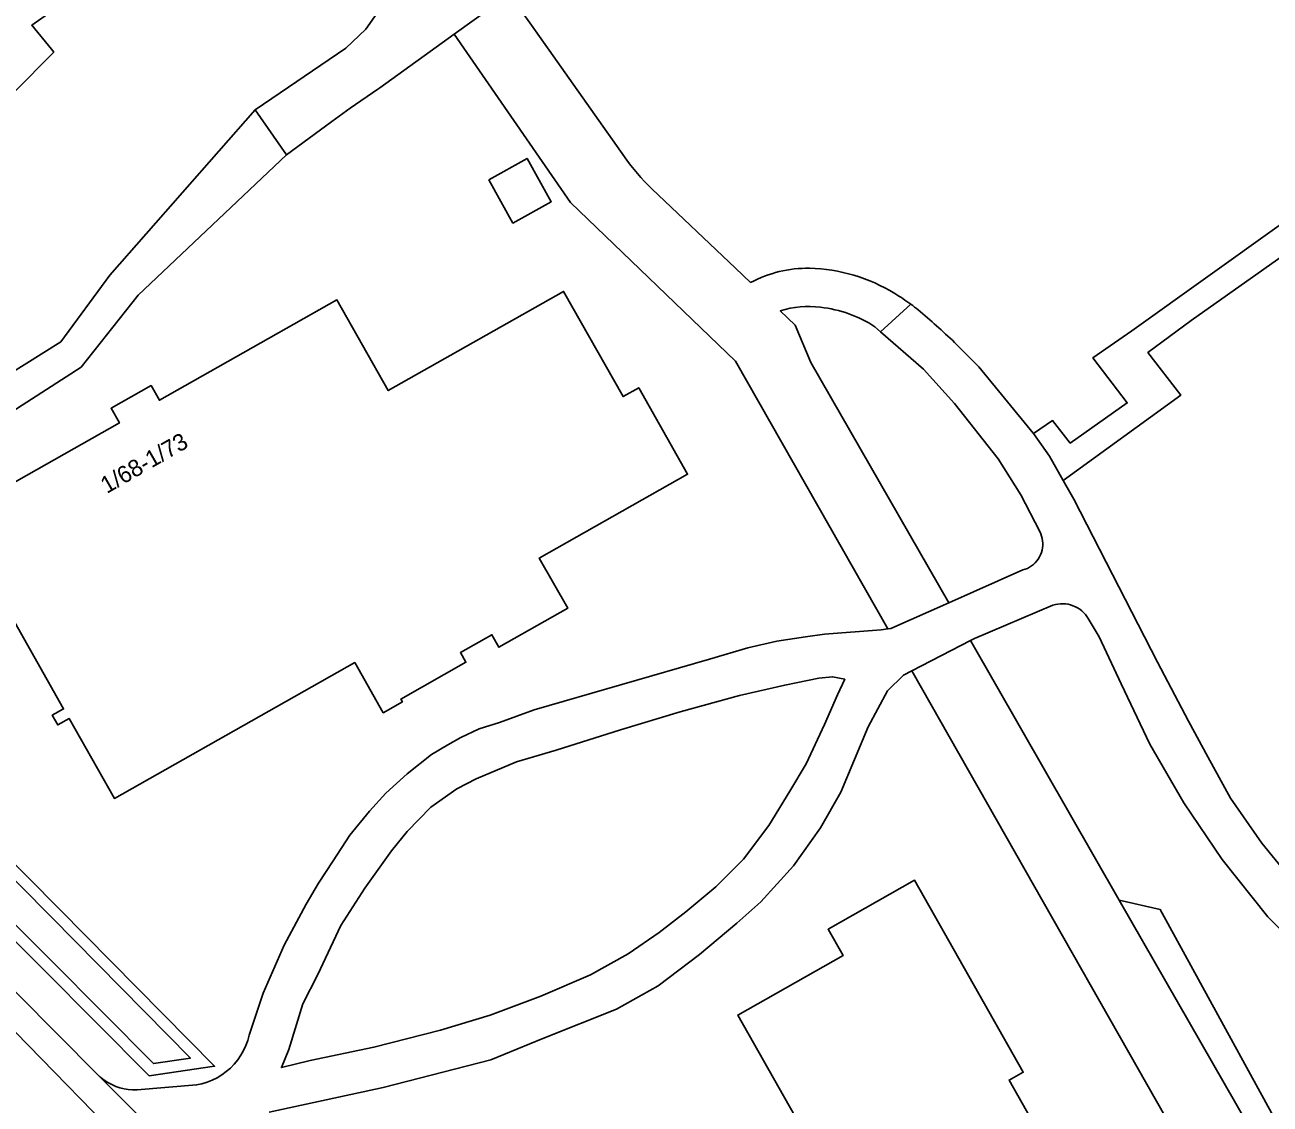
# Model space of a CAD drawing. Extents: x 162788 to 163838, y 385791 to 386523.
# Drawn here: x 162998.4 to 163072, y 386148.1 to 386211.9 of the extents above; entities that cross this region are included whole.
import ezdxf

# ---------------------------------------------------------------- set-up
doc = ezdxf.new("R2010")
doc.units = 0
for name, color, linetype in [('IMGEO_Erf', 7, 'Continuous'), ('IMGEO_Groenvoorziening', 7, 'Continuous'), ('IMGEO_Oever', 7, 'Continuous'), ('IMGEO_Pand', 7, 'Continuous'), ('IMGEO_Pand_nummerreeks', 7, 'Continuous'), ('IMGEO_Parkeervlak_open', 7, 'Continuous'), ('IMGEO_Voetpad_open', 7, 'Continuous'), ('IMGEO_Waterloop', 7, 'Continuous'), ('IMGEO_Woonerf_gesloten', 7, 'Continuous'), ('IMGEO_Woonerf_open', 7, 'Continuous')]:
    doc.layers.add(name, color=color, linetype=linetype)

msp = doc.modelspace()

# ---------------------------------------------------------------- linework, layer by layer
at = {"layer": 'IMGEO_Erf'}
for points in [[(163019.415, 386221.829), (163017.215, 386224.903), (163006.507, 386217.247), (163004.811, 386216.063), (162998.839, 386211.871), (163000, 386210.448), (163000.138, 386210.278), (162990.677, 386200.741), (162991.908, 386199.494), (162983.103, 386190.616), (162967.863, 386205.517), (162976.444, 386214.191), (162973.671, 386216.902), (162977.86, 386221.232), (162975.179, 386223.844)], [(162975.179, 386223.844), (162974.697, 386223.353), (162973.449, 386222.082), (162966.269, 386214.768), (162962.884, 386218.155), (162961.686, 386216.939), (162961.22, 386217.38), (162952.648, 386208.766), (162952.362, 386208.479), (162969.976, 386190.594), (162979.54, 386180.693), (162978.922, 386179.765), (162983.538, 386182.642), (162989.546, 386186.246), (163000.557, 386193.158), (163003.461, 386197.095), (163012.04, 386206.871), (163017.413, 386210.52), (163018.585, 386211.639), (163019.242, 386212.566)], [(163053.386, 386193.116), (163054.816, 386191.673), (163058.026, 386187.749), (163058.046, 386187.721), (163059.184, 386188.499), (163060.221, 386187.16), (163063.596, 386189.539), (163061.561, 386192.213), (163063.865, 386193.803), (163094.896, 386216.008), (163096.436, 386213.921), (163109.744, 386223.185)], [(163027.082, 386213.699), (163028.376, 386211.868), (163033.879, 386204.082)], [(162976.869, 386175.895), (163002.732, 386149.828), (163002.921, 386149.653), (163003.124, 386149.496), (163003.339, 386149.355), (163003.565, 386149.233), (163003.801, 386149.13), (163004.044, 386149.047), (163004.293, 386148.984), (163004.547, 386148.942), (163004.803, 386148.922), (163005.061, 386148.923), (163008.578, 386149.214), (163008.896, 386149.281), (163009.207, 386149.375), (163009.509, 386149.495), (163009.8, 386149.64), (163010.078, 386149.809), (163010.34, 386150.001), (163010.586, 386150.214), (163010.812, 386150.447), (163011.018, 386150.699), (163011.203, 386150.966), (163011.364, 386151.249), (163011.5, 386151.544), (163011.612, 386151.849), (163011.697, 386152.163), (163012.528, 386154.635), (163013.767, 386157.477), (163015.068, 386159.899), (163015.789, 386161.148), (163016.665, 386162.471), (163017.647, 386163.981), (163018.796, 386165.397), (163019.777, 386166.463), (163021.022, 386167.61), (163022.47, 386168.743), (163023.427, 386169.327), (163024.209, 386169.766), (163025.293, 386170.266), (163026.478, 386170.638), (163028.541, 386171.391), (163038.91, 386174.387), (163041.158, 386175.06), (163042.871, 386175.444), (163044.582, 386175.715), (163045.689, 386175.873), (163049.052, 386176.119), (163049.447, 386176.177), (163040.442, 386192.013), (163030.689, 386201.393), (163023.809, 386211.345), (163019.407, 386208.177), (163019.293, 386208.095), (163017.666, 386206.958), (163016.568, 386206.176), (163013.888, 386204.203), (163005.124, 386195.909), (163001.751, 386191.657), (162991.499, 386185.046)], [(163035.49, 386202.19), (163040.437, 386197.514), (163041.332, 386196.659)], [(162993.608, 386182.463), (163004.022, 386188.356), (163003.53, 386189.226), (163005.892, 386190.563), (163006.384, 386189.693), (163016.877, 386195.631), (163019.911, 386190.27), (163030.272, 386196.133), (163033.793, 386189.91), (163034.716, 386190.432), (163037.607, 386185.324), (163028.838, 386180.362), (163030.518, 386177.394), (163026.457, 386175.096), (163026.04, 386175.832), (163024.174, 386174.776), (163024.499, 386174.201), (163020.662, 386172.03), (163020.753, 386171.868), (163019.613, 386171.223), (163017.934, 386174.19), (163003.725, 386166.15), (163001.046, 386170.884), (163000.376, 386170.505), (163000.055, 386171.07), (163000.726, 386171.45), (162995.695, 386180.339)], [(163071.455, 386137.47), (163050.858, 386173.695), (163050.358, 386173.437), (163049.417, 386172.514), (163048.276, 386170.391), (163046.656, 386166.52), (163045.463, 386164.409), (163043.874, 386162.168), (163041.926, 386160.035), (163040.512, 386158.774), (163038.302, 386156.923), (163035.867, 386155.071), (163033.412, 386153.698), (163029.056, 386151.954), (163025.969, 386150.694), (163019.609, 386149.062), (163012.878, 386147.609)], [(163045.461, 386144.702), (163040.571, 386153.344), (163046.793, 386156.865), (163045.912, 386158.423), (163051.02, 386161.314), (163057.442, 386149.967), (163056.61, 386149.496), (163059.436, 386144.503)]]:
    msp.add_lwpolyline(points, dxfattribs=at)
for points in [[(163025.856, 386202.724), (163028.122, 386203.991), (163029.551, 386201.435), (163027.285, 386200.168)], [(163009.646, 386150.318), (163005.787, 386149.75), (162999.516, 386156.061), (162985.265, 386170.371), (162983.184, 386172.461), (162980.008, 386175.65), (162979.797, 386176.339), (162980.054, 386176.979), (162980.589, 386177.518), (162981.556, 386178.158), (162982.352, 386177.855), (162985.467, 386174.749), (162987.558, 386172.662), (163000.485, 386159.606)]]:
    msp.add_lwpolyline(points, close=True, dxfattribs=at)
for centre, radius, start, end in [((163044.202, 386211.24), 12.562, 214.73752, 226.08994), ((163044.727, 386190.267), 7.237, 89.33179, 117.97216), ((163044.561, 386187.409), 10.098, 58.39135, 88.58368), ((163043.713, 386185.761), 11.947, 53.5768, 59.07082), ((163044.12, 386186.343), 11.237, 50.71107, 53.48351), ((163015.763, 386153.237), 54.825, 46.66737, 49.68294)]:
    msp.add_arc(centre, radius, start, end, dxfattribs=at)
at = {"layer": 'IMGEO_Groenvoorziening'}
for points in [[(163091.659, 386211.575), (163067.365, 386194.404), (163064.812, 386192.513), (163066.763, 386189.997), (163059.809, 386184.943), (163060.427, 386183.844), (163065.381, 386174.201), (163067.223, 386170.729), (163068.353, 386168.621), (163069.7, 386166.174), (163071.54, 386163.513), (163073.563, 386161.05)], [(163043.082, 386194.985), (163043.965, 386194.14), (163044.897, 386191.932), (163053.046, 386177.719), (163057.425, 386179.66), (163057.56, 386179.703), (163057.69, 386179.758), (163057.816, 386179.825), (163057.934, 386179.903), (163058.046, 386179.99), (163058.149, 386180.088), (163058.244, 386180.194), (163058.328, 386180.308), (163058.402, 386180.429), (163058.465, 386180.556), (163058.517, 386180.688), (163058.556, 386180.824), (163058.584, 386180.963), (163058.599, 386181.104), (163058.601, 386181.246), (163058.591, 386181.388), (163058.568, 386181.528), (163058.533, 386181.665), (163058.486, 386181.799), (163058.427, 386181.928), (163057.312, 386184.1), (163055.962, 386186.238)], [(163055.962, 386186.238), (163053.384, 386189.497), (163051.558, 386191.528), (163049.012, 386193.748), (163048.679, 386194.039)], [(163074.019, 386157.019), (163071.896, 386159.158), (163069.194, 386162.543), (163066.93, 386165.891), (163064.929, 386169.365), (163063.229, 386172.939), (163061.927, 386175.718), (163061.293, 386176.783), (163061.211, 386176.911), (163061.119, 386177.031), (163061.016, 386177.142), (163060.905, 386177.245), (163060.785, 386177.338), (163060.658, 386177.42), (163060.525, 386177.491), (163060.385, 386177.55), (163060.241, 386177.598), (163060.094, 386177.633), (163059.944, 386177.655), (163059.793, 386177.665), (163059.642, 386177.661), (163059.491, 386177.645), (163059.343, 386177.616), (163059.197, 386177.574), (163054.558, 386175.601), (163054.328, 386175.482), (163063.122, 386160.144), (163065.544, 386159.577), (163072.693, 386146.51)]]:
    msp.add_lwpolyline(points, dxfattribs=at)
msp.add_lwpolyline([(163046.174, 386173.347), (163045.36, 386173.262), (163043.344, 386172.858), (163040.683, 386172.234), (163037.174, 386171.271), (163033.641, 386170.214), (163029.836, 386169.016), (163027.492, 386168.312), (163025.108, 386167.316), (163023.97, 386166.717), (163022.428, 386165.633), (163021.03, 386164.199), (163020.107, 386163.058), (163018.519, 386160.839), (163017.119, 386158.638), (163015.742, 386155.748), (163014.865, 386154.004), (163014.033, 386151.305), (163013.593, 386150.238), (163015.293, 386150.653), (163019.064, 386151.442), (163023.006, 386152.46), (163025.934, 386153.344), (163028.934, 386154.466), (163031.871, 386155.729), (163034.097, 386156.971), (163035.934, 386158.223), (163037.51, 386159.439), (163039.279, 386160.932), (163040.91, 386162.559), (163042.415, 386164.56), (163043.642, 386166.581), (163044.606, 386168.201), (163045.695, 386170.518), (163046.459, 386172.284), (163046.898, 386173.198)], close=True, dxfattribs=at)
for centre, radius, start, end in [((163044.744, 386189.682), 5.558, 82.58997, 107.40355), ((163044.67, 386187.923), 7.313, 56.75475, 83.78879)]:
    msp.add_arc(centre, radius, start, end, dxfattribs=at)
at = {"layer": 'IMGEO_Oever'}
for points in [[(162982.352, 386177.855), (162981.556, 386178.158), (162980.589, 386177.518), (162980.054, 386176.979), (162979.797, 386176.339), (162980.008, 386175.65), (162983.184, 386172.461), (162985.265, 386170.371), (162999.516, 386156.061), (163005.787, 386149.75), (163009.646, 386150.318), (163000.485, 386159.606), (162987.558, 386172.662), (162985.467, 386174.749)], [(162984.985, 386174.266), (162987.075, 386172.181), (163000, 386159.127), (163008.216, 386150.797), (163006.028, 386150.475), (163000, 386156.542), (162985.748, 386170.852), (162983.667, 386172.942), (162980.611, 386176.011), (162980.52, 386176.308), (162980.636, 386176.597), (162981.024, 386176.988), (162981.64, 386177.396), (162981.973, 386177.269)]]:
    msp.add_lwpolyline(points, close=True, dxfattribs=at)
at = {"layer": 'IMGEO_Pand'}
for points in [[(163004.708, 386220.778), (163012.988, 386226.739), (163001.488, 386242.784), (162990.889, 386235.198), (162988.569, 386237.483), (162975.179, 386223.844), (162977.86, 386221.232), (162973.671, 386216.902), (162976.444, 386214.191), (162967.863, 386205.517), (162983.103, 386190.616), (162991.908, 386199.494), (162990.677, 386200.741), (163000.138, 386210.278), (163000, 386210.448), (162998.839, 386211.871), (163004.811, 386216.063), (163002.528, 386219.208), (163004.161, 386220.384)], [(163025.856, 386202.724), (163027.285, 386200.168), (163029.551, 386201.435), (163028.122, 386203.991)]]:
    msp.add_lwpolyline(points, close=True, dxfattribs=at)
for points in [[(162995.695, 386180.339), (163000.726, 386171.45), (163000.055, 386171.07), (163000.376, 386170.505), (163001.046, 386170.884), (163003.725, 386166.15), (163017.934, 386174.19), (163019.613, 386171.223), (163020.753, 386171.868), (163020.662, 386172.03), (163024.499, 386174.201), (163024.174, 386174.776), (163026.04, 386175.832), (163026.457, 386175.096), (163030.518, 386177.394), (163028.838, 386180.362), (163037.607, 386185.324), (163034.716, 386190.432), (163033.793, 386189.91), (163030.272, 386196.133), (163019.911, 386190.27), (163016.877, 386195.631), (163006.384, 386189.693), (163005.892, 386190.563), (163003.53, 386189.226), (163004.022, 386188.356), (162993.608, 386182.463)], [(163059.436, 386144.503), (163056.61, 386149.496), (163057.442, 386149.967), (163051.02, 386161.314), (163045.912, 386158.423), (163046.793, 386156.865), (163040.571, 386153.344), (163045.461, 386144.702)]]:
    msp.add_lwpolyline(points, dxfattribs=at)
at = {"layer": 'IMGEO_Parkeervlak_open'}
msp.add_lwpolyline([(163063.122, 386160.144), (163072.09, 386144.501), (163072.693, 386146.51), (163065.544, 386159.577)], close=True, dxfattribs=at)
at = {"layer": 'IMGEO_Voetpad_open'}
msp.add_lwpolyline([(163094.896, 386216.008), (163063.865, 386193.803), (163061.561, 386192.213), (163063.596, 386189.539), (163060.221, 386187.16), (163059.184, 386188.499), (163058.046, 386187.721), (163058.998, 386186.383), (163059.809, 386184.943), (163066.763, 386189.997), (163064.812, 386192.513), (163067.365, 386194.404), (163091.659, 386211.575), (163093.672, 386208.95), (163094.459, 386209.547), (163094.826, 386209.095), (163091.546, 386206.709), (163094.22, 386203.06), (163098.45, 386206.035), (163095.556, 386210.004), (163098.025, 386211.759), (163097.498, 386212.508)], dxfattribs=at)
at = {"layer": 'IMGEO_Waterloop'}
msp.add_lwpolyline([(162981.973, 386177.269), (162981.64, 386177.396), (162981.024, 386176.988), (162980.636, 386176.597), (162980.52, 386176.308), (162980.611, 386176.011), (162983.667, 386172.942), (162985.748, 386170.852), (163000, 386156.542), (163006.028, 386150.475), (163008.216, 386150.797), (163000, 386159.127), (162987.075, 386172.181), (162984.985, 386174.266)], close=True, dxfattribs=at)
at = {"layer": 'IMGEO_Woonerf_gesloten'}
for points in [[(163019.242, 386212.566), (163018.585, 386211.639), (163017.413, 386210.52), (163012.04, 386206.871), (163013.888, 386204.203), (163016.568, 386206.176), (163017.666, 386206.958), (163019.293, 386208.095), (163019.407, 386208.177), (163023.809, 386211.345), (163027.082, 386213.699)], [(163050.807, 386195.374), (163049.012, 386193.748), (163051.558, 386191.528), (163053.384, 386189.497), (163055.962, 386186.238), (163057.312, 386184.1), (163058.427, 386181.928), (163058.486, 386181.799), (163058.533, 386181.665), (163058.568, 386181.528), (163058.591, 386181.388), (163058.601, 386181.246), (163058.599, 386181.104), (163058.584, 386180.963), (163058.556, 386180.824), (163058.517, 386180.688), (163058.465, 386180.556), (163058.402, 386180.429), (163058.328, 386180.308), (163058.244, 386180.194), (163058.149, 386180.088), (163058.046, 386179.99), (163057.934, 386179.903), (163057.816, 386179.825), (163057.69, 386179.758), (163057.56, 386179.703), (163057.425, 386179.66), (163053.046, 386177.719), (163049.627, 386176.203), (163049.447, 386176.177), (163049.052, 386176.119), (163045.689, 386175.873), (163044.582, 386175.715), (163042.871, 386175.444), (163041.158, 386175.06), (163038.91, 386174.387), (163028.541, 386171.391), (163026.478, 386170.638), (163025.293, 386170.266), (163024.209, 386169.766), (163023.427, 386169.327), (163022.47, 386168.743), (163021.022, 386167.61), (163019.777, 386166.463), (163018.796, 386165.397), (163017.647, 386163.981), (163016.665, 386162.471), (163015.789, 386161.148), (163015.068, 386159.899), (163013.767, 386157.477), (163012.528, 386154.635), (163011.697, 386152.163), (163011.612, 386151.849), (163011.5, 386151.544), (163011.364, 386151.249), (163011.203, 386150.966), (163011.018, 386150.699), (163010.812, 386150.447), (163010.586, 386150.214), (163010.34, 386150.001), (163010.078, 386149.809), (163009.8, 386149.64), (163009.509, 386149.495), (163009.207, 386149.375), (163008.896, 386149.281), (163008.578, 386149.214), (163005.061, 386148.923), (163004.803, 386148.922), (163004.547, 386148.942), (163004.293, 386148.984), (163004.044, 386149.047), (163003.801, 386149.13), (163003.565, 386149.233), (163003.339, 386149.355), (163003.124, 386149.496), (163002.921, 386149.653), (163002.732, 386149.828), (163009.445, 386143.123)], [(163073.563, 386161.05), (163071.54, 386163.513), (163069.7, 386166.174), (163068.353, 386168.621), (163067.223, 386170.729), (163065.381, 386174.201), (163060.427, 386183.844), (163059.809, 386184.943), (163058.998, 386186.383), (163058.046, 386187.721), (163058.026, 386187.749), (163054.816, 386191.673), (163053.386, 386193.116)], [(163012.878, 386147.609), (163019.609, 386149.062), (163025.969, 386150.694), (163029.056, 386151.954), (163033.412, 386153.698), (163035.867, 386155.071), (163038.302, 386156.923), (163040.512, 386158.774), (163041.926, 386160.035), (163043.874, 386162.168), (163045.463, 386164.409), (163046.656, 386166.52), (163048.276, 386170.391), (163049.417, 386172.514), (163050.358, 386173.437), (163050.858, 386173.695), (163054.328, 386175.482), (163054.558, 386175.601), (163059.197, 386177.574), (163059.343, 386177.616), (163059.491, 386177.645), (163059.642, 386177.661), (163059.793, 386177.665), (163059.944, 386177.655), (163060.094, 386177.633), (163060.241, 386177.598), (163060.385, 386177.55), (163060.525, 386177.491), (163060.658, 386177.42), (163060.785, 386177.338), (163060.905, 386177.245), (163061.016, 386177.142), (163061.119, 386177.031), (163061.211, 386176.911), (163061.293, 386176.783), (163061.927, 386175.718), (163063.229, 386172.939), (163064.929, 386169.365), (163066.93, 386165.891), (163069.194, 386162.543), (163071.896, 386159.158), (163074.019, 386157.019)], [(162998.224, 386145.839), (162998.479, 386145.875), (163001.755, 386146.179), (163002.155, 386146.184), (163002.554, 386146.154), (163002.948, 386146.09), (163003.336, 386145.991), (163003.713, 386145.859), (163004.078, 386145.694), (163004.426, 386145.499), (163004.756, 386145.273), (162997.883, 386152.342)]]:
    msp.add_lwpolyline(points, dxfattribs=at)
msp.add_lwpolyline([(163046.898, 386173.198), (163046.459, 386172.284), (163045.695, 386170.518), (163044.606, 386168.201), (163043.642, 386166.581), (163042.415, 386164.56), (163040.91, 386162.559), (163039.279, 386160.932), (163037.51, 386159.439), (163035.934, 386158.223), (163034.097, 386156.971), (163031.871, 386155.729), (163028.934, 386154.466), (163025.934, 386153.344), (163023.006, 386152.46), (163019.064, 386151.442), (163015.293, 386150.653), (163013.593, 386150.238), (163014.033, 386151.305), (163014.865, 386154.004), (163015.742, 386155.748), (163017.119, 386158.638), (163018.519, 386160.839), (163020.107, 386163.058), (163021.03, 386164.199), (163022.428, 386165.633), (163023.97, 386166.717), (163025.108, 386167.316), (163027.492, 386168.312), (163029.836, 386169.016), (163033.641, 386170.214), (163037.174, 386171.271), (163040.683, 386172.234), (163043.344, 386172.858), (163045.36, 386173.262), (163046.174, 386173.347)], close=True, dxfattribs=at)
for centre, radius, start, end in [((163044.12, 386186.343), 11.237, 50.71107, 53.48351), ((163015.763, 386153.237), 54.825, 46.66737, 49.68294)]:
    msp.add_arc(centre, radius, start, end, dxfattribs=at)
at = {"layer": 'IMGEO_Woonerf_open'}
for points in [[(163033.879, 386204.082), (163028.376, 386211.868), (163027.082, 386213.699), (163023.809, 386211.345), (163030.689, 386201.393), (163040.442, 386192.013), (163049.447, 386176.177), (163049.627, 386176.203), (163053.046, 386177.719), (163044.897, 386191.932), (163043.965, 386194.14), (163043.082, 386194.985)], [(162937.328, 386213.523), (162970.367, 386180.135), (162997.883, 386152.342), (163004.756, 386145.273), (163006.091, 386144.101), (163009.12, 386141.019), (163031.422, 386118.469), (163036.332, 386113.744), (163041.321, 386108.185), (163041.525, 386108.014), (163041.713, 386107.825), (163049.21, 386100.56)], [(162991.499, 386185.046), (163001.751, 386191.657), (163005.124, 386195.909), (163013.888, 386204.203), (163012.04, 386206.871), (163003.461, 386197.095), (163000.557, 386193.158), (162989.546, 386186.246)], [(163041.332, 386196.659), (163040.437, 386197.514), (163035.49, 386202.19)], [(163048.679, 386194.039), (163049.012, 386193.748), (163050.807, 386195.374)], [(163057.742, 386094.28), (163044.609, 386107.498), (163042.009, 386110.032), (163038.435, 386113.764), (163036.77, 386115.488), (163011.853, 386140.665), (163009.745, 386142.841), (163009.589, 386142.976), (163009.445, 386143.123), (163002.732, 386149.828), (162976.869, 386175.895)]]:
    msp.add_lwpolyline(points, dxfattribs=at)
msp.add_lwpolyline([(163063.122, 386160.144), (163054.328, 386175.482), (163050.858, 386173.695), (163071.455, 386137.47), (163071.555, 386137.294), (163074.529, 386140.723), (163074.174, 386140.866), (163072.09, 386144.501)], close=True, dxfattribs=at)
for centre, radius, start, end in [((163044.202, 386211.24), 12.562, 214.73752, 226.08994), ((163044.727, 386190.267), 7.237, 89.33179, 117.97216), ((163044.561, 386187.409), 10.098, 58.39135, 88.58368), ((163043.713, 386185.761), 11.947, 53.5768, 59.07082), ((163044.744, 386189.682), 5.558, 82.58997, 107.40355), ((163044.67, 386187.923), 7.313, 56.75475, 83.78879)]:
    msp.add_arc(centre, radius, start, end, dxfattribs=at)

# ---------------------------------------------------------------- texts
at = {"layer": 'IMGEO_Pand_nummerreeks'}
msp.add_text('1/68-1/73', height=1, rotation=29.8512, dxfattribs=at).set_placement((163003.275, 386184.15))

doc.saveas('drawing.dxf')
